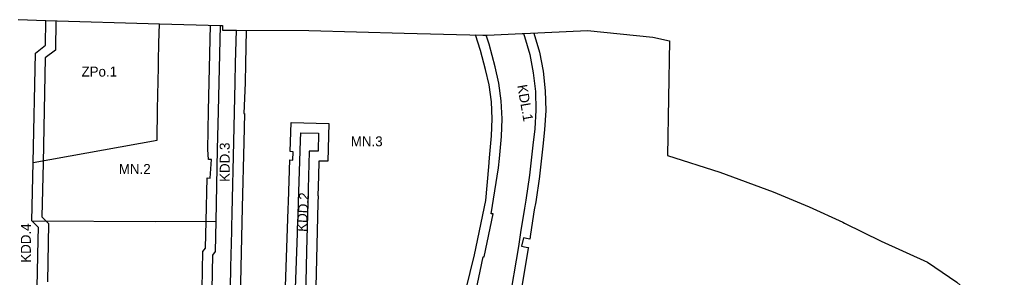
# Model space of a CAD drawing. Extents: x 7414808 to 7417449, y 5544732 to 5546764.
# Drawn here: x 7415779 to 7416266.3, y 5546060.4 to 5546189.6 of the extents above; entities that cross this region are included whole.
import ezdxf

# ---------------------------------------------------------------- set-up
doc = ezdxf.new("R2010")
doc.units = 0
for name, color, linetype in [('LIN_Linie Rozgraniczajace', 7, 'Continuous'), ('LIN_nieprzekraczale linie zabudowy', 7, 'Continuous'), ('TXT_Oznaczenia Przeznaczenia', 7, 'Continuous')]:
    doc.layers.add(name, color=color, linetype=linetype)

msp = doc.modelspace()

# ---------------------------------------------------------------- linework, layer by layer
at = {"layer": 'LIN_Linie Rozgraniczajace'}
for p, q in [((7415778.34, 5546189.58), (7415792.34, 5546189.15)), ((7415792.34, 5546189.15), (7415849.22, 5546187.38)), ((7415849.22, 5546187.38), (7415879.82, 5546186.61)), ((7415785.3, 5546088.86), (7415785.91, 5546117.94))]:
    msp.add_line(p, q, dxfattribs=at)
for points in [[(7415785.91, 5546117.94), (7415787.06, 5546172.8), (7415792.12, 5546176.74), (7415792.34, 5546189.15)], [(7415785.91, 5546117.94), (7415848.06, 5546129.16), (7415848.33, 5546144.72), (7415848.7, 5546165.64), (7415848.77, 5546168.73), (7415848.99, 5546177.78), (7415849.22, 5546187.38)], [(7415877.59, 5546088.6), (7415878.41, 5546124.43), (7415878.85, 5546143.73), (7415879.82, 5546186.61)], [(7415879.82, 5546186.61), (7415880.85, 5546186.59), (7415880.82, 5546184.28), (7415887.77, 5546184.25)], [(7415885.69, 5546092.7), (7415886.5, 5546128.27), (7415887.17, 5546158.02), (7415887.39, 5546167.67), (7415887.77, 5546184.25)], [(7415887.77, 5546184.25), (7415924.19, 5546184.06), (7415971.84, 5546182.77), (7416011.28, 5546181.79), (7416012.98, 5546181.74)], [(7416000, 5545999.56), (7416007.01, 5546046.39), (7416007.77, 5546053.27), (7416011.53, 5546070.75), (7416012.03, 5546070.7), (7416016.43, 5546092.22), (7416015.51, 5546092.28), (7416019.25, 5546115.26), (7416019.68, 5546119.96), (7416020.64, 5546130.99), (7416021.01, 5546139.92), (7416020.58, 5546148.86), (7416019.36, 5546157.71), (7416017.52, 5546165.82), (7416014.43, 5546177.2), (7416012.98, 5546181.74)], [(7416012.98, 5546181.74), (7416013.48, 5546181.73), (7416030.98, 5546182.53), (7416031.71, 5546182.56)], [(7416031.71, 5546182.56), (7416032.23, 5546181.11), (7416034.82, 5546172.09), (7416036.63, 5546162.89), (7416037.66, 5546153.57), (7416037.89, 5546144.2), (7416037.31, 5546134.83), (7416036.47, 5546126.72), (7416035.62, 5546119.19), (7416034.78, 5546111.66), (7416032.88, 5546099.09), (7416032.19, 5546095.15), (7416030.26, 5546082.93), (7416029.17, 5546076.02), (7416024.41, 5546047.6), (7416023.18, 5546038.06), (7416019.9, 5546021.33), (7416016.59, 5546010.05), (7416014.56, 5545997.73), (7416015.33, 5545995.49)], [(7416031.71, 5546182.56), (7416063.73, 5546184.03), (7416096.6, 5546180.73), (7416104.92, 5546178.85), (7416103.96, 5546121.51), (7416130.11, 5546113.16), (7416156.81, 5546103.29), (7416174.89, 5546095.8), (7416191.75, 5546088.18), (7416192.64, 5546087.68), (7416211.01, 5546078.61), (7416234.18, 5546068.04), (7416248.86, 5546058.11), (7416257.56, 5546050.25), (7416266.33, 5546042.67), (7416254.64, 5546013.41), (7416236.06, 5545976.82), (7416225.54, 5545957.13), (7416215, 5545936.65)], [(7415918.71, 5546091.48), (7415918.95, 5546098.1), (7415919.91, 5546128.95), (7415920.03, 5546132.92), (7415929.03, 5546132.64), (7415928.75, 5546123.64), (7415924.7, 5546123.6), (7415924.31, 5546123.6), (7415924.15, 5546116.95), (7415924.02, 5546111.29), (7415923.61, 5546097.93), (7415923.01, 5546073.56), (7415922.63, 5546058.16), (7415922.58, 5546056.01), (7415921.81, 5546049.39), (7415920.6, 5546000.18)], [(7415786.28, 5545973), (7415782.94, 5545976.32), (7415783.43, 5545999.34), (7415786.84, 5546000.16), (7415788.5, 5546079.24), (7415788.63, 5546085.44), (7415785.3, 5546088.86)], [(7415785.3, 5546088.86), (7415847.21, 5546088.53), (7415877.59, 5546088.6)], [(7415872.46, 5545994.8), (7415875.55, 5545998.59), (7415876.38, 5546035.06), (7415875.3, 5546037.23), (7415875.94, 5546071.67), (7415877.25, 5546073.42), (7415877.59, 5546088.6)], [(7415885.49, 5546083.7), (7415885.53, 5546085.7), (7415885.69, 5546092.7)], [(7415918.4, 5546082.49), (7415918.48, 5546084.8), (7415918.71, 5546091.48)], [(7415886.52, 5545997.16), (7415883.58, 5545999.68), (7415884.13, 5546024.12), (7415884.54, 5546042.1), (7415884.6, 5546044.49), (7415885.08, 5546065.59), (7415885.49, 5546083.7)], [(7415916.2, 5545999.89), (7415916.6, 5546023.36), (7415916.91, 5546041.3), (7415918.4, 5546082.49)]]:
    msp.add_lwpolyline(points, dxfattribs=at)
at = {"layer": 'LIN_nieprzekraczale linie zabudowy'}
for points in [[(7415797.34, 5546189.06), (7415797.08, 5546174.26), (7415792.01, 5546170.32), (7415790.91, 5546117.76), (7415790.34, 5546090.85), (7415793.67, 5546087.43), (7415793.06, 5546058.23)], [(7415870.28, 5546036.1), (7415870.97, 5546073.38), (7415872.29, 5546075.13), (7415872.6, 5546088.71), (7415873.08, 5546110.26), (7415874.68, 5546110.21), (7415875.27, 5546119.47), (7415873.85, 5546119.56), (7415873.41, 5546124.55), (7415873.85, 5546143.84), (7415874.82, 5546186.74)], [(7415892.77, 5546184.13), (7415892.39, 5546167.56), (7415892.17, 5546157.91), (7415891.52, 5546142.56), (7415891.82, 5546142.54), (7415891.5, 5546128.15), (7415890.76, 5546095.52)], [(7416002.83, 5546054.07), (7416007.15, 5546071.79), (7416012.81, 5546098.89), (7416014.29, 5546115.89), (7416014.7, 5546120.39), (7416015.65, 5546131.31), (7416016, 5546139.91), (7416015.6, 5546148.39), (7416014.44, 5546156.82), (7416012.67, 5546164.61), (7416010.08, 5546174.13), (7416007.71, 5546181.87)], [(7416036.94, 5546182.8), (7416039.68, 5546173.27), (7416041.58, 5546163.65), (7416042.65, 5546153.91), (7416042.89, 5546144.1), (7416042.3, 5546134.42), (7416041.44, 5546126.2), (7416039.75, 5546111.1), (7416039.72, 5546110.91), (7416037.82, 5546098.34), (7416037.81, 5546098.23), (7416037.13, 5546094.37), (7416035.2, 5546082.15), (7416035.2, 5546082.15), (7416034.81, 5546079.66), (7416034.08, 5546079.82), (7416031.75, 5546080.33), (7416030.79, 5546076.19), (7416033.12, 5546075.68), (7416034.14, 5546075.44), (7416034.1, 5546075.19), (7416029.36, 5546046.87)], [(7415913.82, 5546094.66), (7415913.95, 5546098.28), (7415914.61, 5546119.28), (7415916.02, 5546119.19), (7415916.31, 5546123.36), (7415914.74, 5546123.54), (7415915.19, 5546138.07), (7415934.18, 5546137.48), (7415933.6, 5546118.69), (7415929.19, 5546118.65), (7415929.02, 5546111.15), (7415928.54, 5546101.36), (7415928.71, 5546101.31), (7415928.61, 5546097.79), (7415927.57, 5546055.67)], [(7415889.54, 5546041.99), (7415889.13, 5546024), (7415888.94, 5546015.32), (7415885.81, 5546015.38), (7415885.66, 5546009.07), (7415888.79, 5546008.99), (7415888.64, 5546002.44), (7415893.07, 5546002.97), (7415911.27, 5546004.49), (7415911.91, 5546041.44), (7415913.83, 5546094.61)], [(7415890.76, 5546095.52), (7415890.07, 5546065.48), (7415889.54, 5546041.99)]]:
    msp.add_lwpolyline(points, dxfattribs=at)

# ---------------------------------------------------------------- texts
at = {"layer": 'TXT_Oznaczenia Przeznaczenia'}
for s, p in [('ZPo.1', (7415810.15, 5546161)), ('MN.3', (7415945.13, 5546126.08)), ('MN.2', (7415828.86, 5546112.25))]:
    msp.add_text(s, height=5, dxfattribs=at).set_placement(p)
for s, rotation, p in [('KDL.1', 280, (7416028.53, 5546156.53)), ('KDD.3', 90, (7415884.45, 5546108.27)), ('KDD.2', 86.1445, (7415922.98, 5546083.15)), ('KDD.4', 90, (7415784.76, 5546067.8))]:
    msp.add_text(s, height=5, rotation=rotation, dxfattribs=at).set_placement(p)

doc.saveas('drawing.dxf')
